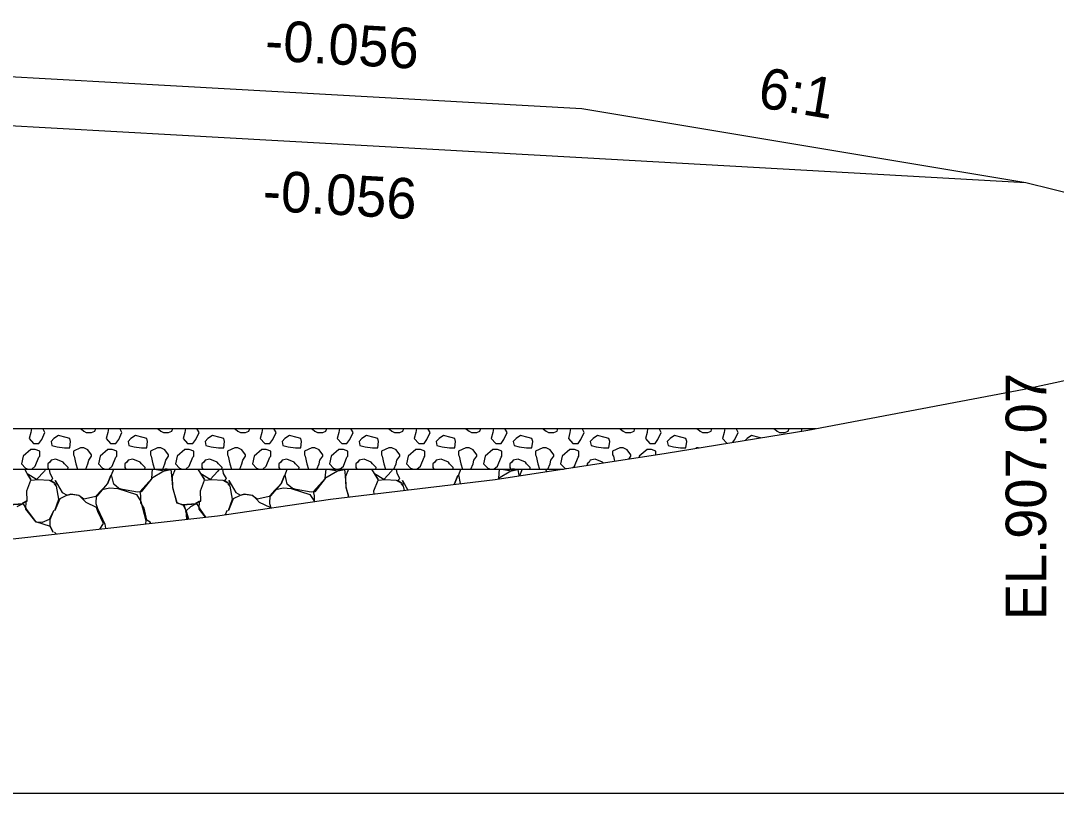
# Model space of a CAD drawing. Extents: x -26 to 4781, y -31 to 24738.
# Drawn here: x 2308.16 to 2333.7, y 8000 to 8019.06 of the extents above; entities that cross this region are included whole.
import ezdxf

# ---------------------------------------------------------------- set-up
doc = ezdxf.new("R2010")
doc.units = 0
for name, color, linetype in [('DESIGN - SHEET - Light Grid', 7, 'Continuous'), ('DESIGN - TRANSPORTATION - Proposed Layout Patterning', 7, 'Continuous'), ('DESIGN - TYPICAL - Finished Grade and Subgrade', 7, 'Continuous'), ('DESIGN - TYPICAL - Finished Grade Slopes Text', 7, 'Continuous'), ('DESIGN - TYPICAL - Subgrade Cross Slope Text', 7, 'Continuous'), ('DESIGN - TYPICAL - Subgrade Tie Text', 7, 'Continuous'), ('GEOTECHNICAL – SCRATCH – Level 1', 7, 'Continuous'), ('SURVEY - GROUND - Top of Ground', 7, 'Continuous')]:
    doc.layers.add(name, color=color, linetype=linetype)

msp = doc.modelspace()

# ---------------------------------------------------------------- linework, layer by layer
at = {"layer": 'DESIGN - SHEET - Light Grid'}
msp.add_line((2300, 8000), (2600, 8000), dxfattribs=at)
at = {"layer": 'DESIGN - TRANSPORTATION - Proposed Layout Patterning'}
for p, q in [((2308.423, 8009), (2308.407, 8008.901)), ((2310.323, 8009), (2310.307, 8008.901)), ((2312.223, 8009), (2312.207, 8008.901)), ((2314.123, 8009), (2314.107, 8008.901)), ((2316.023, 8009), (2316.007, 8008.901)), ((2317.923, 8009), (2317.907, 8008.901)), ((2319.823, 8009), (2319.807, 8008.901)), ((2321.723, 8009), (2321.707, 8008.901)), ((2323.623, 8009), (2323.607, 8008.901)), ((2325.523, 8009), (2325.507, 8008.901)), ((2327.423, 8009), (2327.413, 8008.937)), ((2327.71, 8008.989), (2327.704, 8009)), ((2308.407, 8008.481), (2308.217, 8008.321)), ((2310.307, 8008.481), (2310.117, 8008.321)), ((2312.207, 8008.481), (2312.017, 8008.321)), ((2314.107, 8008.481), (2313.917, 8008.321)), ((2316.007, 8008.481), (2315.817, 8008.321)), ((2317.907, 8008.481), (2317.717, 8008.321)), ((2319.807, 8008.481), (2319.617, 8008.321)), ((2321.707, 8008.481), (2321.517, 8008.321)), ((2323.607, 8008.481), (2323.417, 8008.321)), ((2309.457, 8008.351), (2309.477, 8008.321)), ((2311.357, 8008.351), (2311.377, 8008.321)), ((2313.257, 8008.351), (2313.277, 8008.321)), ((2315.157, 8008.351), (2315.177, 8008.321)), ((2317.057, 8008.351), (2317.077, 8008.321)), ((2318.957, 8008.351), (2318.977, 8008.321)), ((2320.857, 8008.351), (2320.877, 8008.321)), ((2322.523, 8008.15), (2322.507, 8008.171)), ((2322.757, 8008.351), (2322.777, 8008.321)), ((2322.777, 8008.321), (2322.804, 8008.193)), ((2323.156, 8008.248), (2323.207, 8008.321)), ((2323.417, 8008.321), (2323.41, 8008.287)), ((2320.528, 8008), (2320.458, 8007.833)), ((2321.135, 8007.937), (2321.1, 8008))]:
    msp.add_line(p, q, dxfattribs=at)
for points in [[(2308.407, 8008.901), (2308.367, 8008.751), (2308.477, 8008.631), (2308.607, 8008.631), (2308.677, 8008.731), (2308.757, 8008.901), (2308.704, 8009)], [(2309.609, 8009), (2309.657, 8008.981), (2309.717, 8008.931)], [(2309.717, 8008.931), (2309.777, 8008.901), (2309.907, 8008.901), (2309.987, 8008.931), (2310.01, 8009)], [(2310.307, 8008.901), (2310.267, 8008.751), (2310.377, 8008.631), (2310.507, 8008.631), (2310.577, 8008.731), (2310.657, 8008.901), (2310.604, 8009)], [(2311.509, 8009), (2311.557, 8008.981), (2311.617, 8008.931)], [(2311.617, 8008.931), (2311.677, 8008.901), (2311.807, 8008.901), (2311.887, 8008.931), (2311.91, 8009)], [(2312.207, 8008.901), (2312.167, 8008.751), (2312.277, 8008.631), (2312.407, 8008.631), (2312.477, 8008.731), (2312.557, 8008.901), (2312.504, 8009)], [(2313.409, 8009), (2313.457, 8008.981), (2313.517, 8008.931)], [(2313.517, 8008.931), (2313.577, 8008.901), (2313.707, 8008.901), (2313.787, 8008.931), (2313.81, 8009)], [(2314.107, 8008.901), (2314.067, 8008.751), (2314.177, 8008.631), (2314.307, 8008.631), (2314.377, 8008.731), (2314.457, 8008.901), (2314.404, 8009)], [(2315.309, 8009), (2315.357, 8008.981), (2315.417, 8008.931)], [(2315.417, 8008.931), (2315.477, 8008.901), (2315.607, 8008.901), (2315.687, 8008.931), (2315.71, 8009)], [(2316.007, 8008.901), (2315.967, 8008.751), (2316.077, 8008.631), (2316.207, 8008.631), (2316.277, 8008.731), (2316.357, 8008.901), (2316.304, 8009)], [(2317.209, 8009), (2317.257, 8008.981), (2317.317, 8008.931)], [(2317.317, 8008.931), (2317.377, 8008.901), (2317.507, 8008.901), (2317.587, 8008.931), (2317.61, 8009)], [(2317.907, 8008.901), (2317.867, 8008.751), (2317.977, 8008.631), (2318.107, 8008.631), (2318.177, 8008.731), (2318.257, 8008.901), (2318.204, 8009)], [(2319.109, 8009), (2319.157, 8008.981), (2319.217, 8008.931)], [(2319.217, 8008.931), (2319.277, 8008.901), (2319.407, 8008.901), (2319.487, 8008.931), (2319.51, 8009)], [(2319.807, 8008.901), (2319.767, 8008.751), (2319.877, 8008.631), (2320.007, 8008.631), (2320.077, 8008.731), (2320.157, 8008.901), (2320.104, 8009)], [(2321.009, 8009), (2321.057, 8008.981), (2321.117, 8008.931)], [(2321.117, 8008.931), (2321.177, 8008.901), (2321.307, 8008.901), (2321.387, 8008.931), (2321.41, 8009)], [(2321.707, 8008.901), (2321.667, 8008.751), (2321.777, 8008.631), (2321.907, 8008.631), (2321.977, 8008.731), (2322.057, 8008.901), (2322.004, 8009)], [(2322.909, 8009), (2322.957, 8008.981), (2323.017, 8008.931)], [(2323.017, 8008.931), (2323.077, 8008.901), (2323.207, 8008.901), (2323.287, 8008.931), (2323.31, 8009)], [(2323.607, 8008.901), (2323.567, 8008.751), (2323.677, 8008.631), (2323.807, 8008.631), (2323.877, 8008.731), (2323.957, 8008.901), (2323.904, 8009)], [(2324.809, 8009), (2324.857, 8008.981), (2324.917, 8008.931)], [(2324.917, 8008.931), (2324.977, 8008.901), (2325.107, 8008.901), (2325.187, 8008.931), (2325.21, 8009)], [(2325.507, 8008.901), (2325.467, 8008.751), (2325.574, 8008.635)], [(2325.728, 8008.66), (2325.777, 8008.731), (2325.857, 8008.901), (2325.804, 8009)], [(2326.709, 8009), (2326.757, 8008.981), (2326.817, 8008.931)], [(2326.817, 8008.931), (2326.877, 8008.901), (2327.007, 8008.901), (2327.087, 8008.931), (2327.11, 8009)], [(2309.367, 8008.751), (2309.277, 8008.781), (2309.087, 8008.831), (2308.977, 8008.751), (2308.907, 8008.681), (2308.927, 8008.581), (2309.057, 8008.551), (2309.237, 8008.521), (2309.367, 8008.521), (2309.387, 8008.681), (2309.367, 8008.751)], [(2311.267, 8008.751), (2311.177, 8008.781), (2310.987, 8008.831), (2310.877, 8008.751), (2310.807, 8008.681), (2310.827, 8008.581), (2310.957, 8008.551), (2311.137, 8008.521), (2311.267, 8008.521), (2311.287, 8008.681), (2311.267, 8008.751)], [(2313.167, 8008.751), (2313.077, 8008.781), (2312.887, 8008.831), (2312.777, 8008.751), (2312.707, 8008.681), (2312.727, 8008.581), (2312.857, 8008.551), (2313.037, 8008.521), (2313.167, 8008.521), (2313.187, 8008.681), (2313.167, 8008.751)], [(2315.067, 8008.751), (2314.977, 8008.781), (2314.787, 8008.831), (2314.677, 8008.751), (2314.607, 8008.681), (2314.627, 8008.581), (2314.757, 8008.551), (2314.937, 8008.521), (2315.067, 8008.521), (2315.087, 8008.681), (2315.067, 8008.751)], [(2316.967, 8008.751), (2316.877, 8008.781), (2316.687, 8008.831), (2316.577, 8008.751), (2316.507, 8008.681), (2316.527, 8008.581), (2316.657, 8008.551), (2316.837, 8008.521), (2316.967, 8008.521), (2316.987, 8008.681), (2316.967, 8008.751)], [(2318.867, 8008.751), (2318.777, 8008.781), (2318.587, 8008.831), (2318.477, 8008.751), (2318.407, 8008.681), (2318.427, 8008.581), (2318.557, 8008.551), (2318.737, 8008.521), (2318.867, 8008.521), (2318.887, 8008.681), (2318.867, 8008.751)], [(2320.767, 8008.751), (2320.677, 8008.781), (2320.487, 8008.831), (2320.377, 8008.751), (2320.307, 8008.681), (2320.327, 8008.581), (2320.457, 8008.551), (2320.637, 8008.521), (2320.767, 8008.521), (2320.787, 8008.681), (2320.767, 8008.751)], [(2322.667, 8008.751), (2322.577, 8008.781), (2322.387, 8008.831), (2322.277, 8008.751), (2322.207, 8008.681), (2322.227, 8008.581), (2322.357, 8008.551), (2322.537, 8008.521), (2322.667, 8008.521), (2322.687, 8008.681), (2322.667, 8008.751)], [(2324.567, 8008.751), (2324.477, 8008.781), (2324.287, 8008.831), (2324.177, 8008.751), (2324.107, 8008.681), (2324.127, 8008.581), (2324.257, 8008.551), (2324.437, 8008.521), (2324.567, 8008.521), (2324.587, 8008.681), (2324.567, 8008.751)], [(2326.405, 8008.771), (2326.377, 8008.781), (2326.187, 8008.831), (2326.077, 8008.751), (2326.038, 8008.711)], [(2308.627, 8008.321), (2308.627, 8008.441), (2308.517, 8008.481), (2308.407, 8008.481)], [(2309.717, 8008.521), (2309.657, 8008.521), (2309.637, 8008.521), (2309.457, 8008.441), (2309.457, 8008.351)], [(2309.907, 8008.321), (2309.907, 8008.351), (2309.817, 8008.471), (2309.717, 8008.521)], [(2310.527, 8008.321), (2310.527, 8008.441), (2310.417, 8008.481), (2310.307, 8008.481)], [(2311.617, 8008.521), (2311.557, 8008.521), (2311.537, 8008.521), (2311.357, 8008.441), (2311.357, 8008.351)], [(2311.807, 8008.321), (2311.807, 8008.351), (2311.717, 8008.471), (2311.617, 8008.521)], [(2312.427, 8008.321), (2312.427, 8008.441), (2312.317, 8008.481), (2312.207, 8008.481)], [(2313.517, 8008.521), (2313.457, 8008.521), (2313.437, 8008.521), (2313.257, 8008.441), (2313.257, 8008.351)], [(2313.707, 8008.321), (2313.707, 8008.351), (2313.617, 8008.471), (2313.517, 8008.521)], [(2314.327, 8008.321), (2314.327, 8008.441), (2314.217, 8008.481), (2314.107, 8008.481)], [(2315.417, 8008.521), (2315.357, 8008.521), (2315.337, 8008.521), (2315.157, 8008.441), (2315.157, 8008.351)], [(2315.607, 8008.321), (2315.607, 8008.351), (2315.517, 8008.471), (2315.417, 8008.521)], [(2316.227, 8008.321), (2316.227, 8008.441), (2316.117, 8008.481), (2316.007, 8008.481)], [(2317.317, 8008.521), (2317.257, 8008.521), (2317.237, 8008.521), (2317.057, 8008.441), (2317.057, 8008.351)], [(2317.507, 8008.321), (2317.507, 8008.351), (2317.417, 8008.471), (2317.317, 8008.521)], [(2318.127, 8008.321), (2318.127, 8008.441), (2318.017, 8008.481), (2317.907, 8008.481)], [(2319.217, 8008.521), (2319.157, 8008.521), (2319.137, 8008.521), (2318.957, 8008.441), (2318.957, 8008.351)], [(2319.407, 8008.321), (2319.407, 8008.351), (2319.317, 8008.471), (2319.217, 8008.521)], [(2320.027, 8008.321), (2320.027, 8008.441), (2319.917, 8008.481), (2319.807, 8008.481)], [(2321.117, 8008.521), (2321.057, 8008.521), (2321.037, 8008.521), (2320.857, 8008.441), (2320.857, 8008.351)], [(2321.307, 8008.321), (2321.307, 8008.351), (2321.217, 8008.471), (2321.117, 8008.521)], [(2321.927, 8008.321), (2321.927, 8008.441), (2321.817, 8008.481), (2321.707, 8008.481)], [(2323.017, 8008.521), (2322.957, 8008.521), (2322.937, 8008.521), (2322.757, 8008.441), (2322.757, 8008.351)], [(2323.207, 8008.321), (2323.207, 8008.351), (2323.117, 8008.471), (2323.017, 8008.521)], [(2323.827, 8008.351), (2323.827, 8008.441), (2323.717, 8008.481), (2323.607, 8008.481)], [(2324.879, 8008.521), (2324.857, 8008.521), (2324.837, 8008.521), (2324.813, 8008.51)], [(2308.217, 8008.321), (2308.177, 8008.131), (2308.277, 8008.021), (2308.344, 8008)], [(2308.431, 8008), (2308.517, 8008.071), (2308.607, 8008.291), (2308.627, 8008.321)], [(2309.207, 8008.171), (2309.027, 8008.241), (2308.907, 8008.221), (2308.877, 8008.171), (2308.827, 8008.131), (2308.827, 8008.041), (2308.848, 8008)], [(2309.322, 8008), (2309.327, 8008.041), (2309.237, 8008.131), (2309.207, 8008.171)], [(2309.477, 8008.321), (2309.517, 8008.131), (2309.559, 8008)], [(2309.765, 8008), (2309.817, 8008.131), (2309.837, 8008.221), (2309.907, 8008.321)], [(2310.117, 8008.321), (2310.077, 8008.131), (2310.177, 8008.021), (2310.244, 8008)], [(2310.331, 8008), (2310.417, 8008.071), (2310.507, 8008.291), (2310.527, 8008.321)], [(2311.107, 8008.171), (2310.927, 8008.241), (2310.807, 8008.221), (2310.777, 8008.171), (2310.727, 8008.131), (2310.727, 8008.041), (2310.748, 8008)], [(2311.222, 8008), (2311.227, 8008.041), (2311.137, 8008.131), (2311.107, 8008.171)], [(2311.377, 8008.321), (2311.417, 8008.131), (2311.459, 8008)], [(2311.665, 8008), (2311.717, 8008.131), (2311.737, 8008.221), (2311.807, 8008.321)], [(2312.017, 8008.321), (2311.977, 8008.131), (2312.077, 8008.021), (2312.144, 8008)], [(2312.231, 8008), (2312.317, 8008.071), (2312.407, 8008.291), (2312.427, 8008.321)], [(2313.007, 8008.171), (2312.827, 8008.241), (2312.707, 8008.221), (2312.677, 8008.171), (2312.627, 8008.131), (2312.627, 8008.041), (2312.648, 8008)], [(2313.122, 8008), (2313.127, 8008.041), (2313.037, 8008.131), (2313.007, 8008.171)], [(2313.277, 8008.321), (2313.317, 8008.131), (2313.359, 8008)], [(2313.565, 8008), (2313.617, 8008.131), (2313.637, 8008.221), (2313.707, 8008.321)], [(2313.917, 8008.321), (2313.877, 8008.131), (2313.977, 8008.021), (2314.044, 8008)], [(2314.131, 8008), (2314.217, 8008.071), (2314.307, 8008.291), (2314.327, 8008.321)], [(2314.907, 8008.171), (2314.727, 8008.241), (2314.607, 8008.221), (2314.577, 8008.171), (2314.527, 8008.131), (2314.527, 8008.041), (2314.548, 8008)], [(2315.022, 8008), (2315.027, 8008.041), (2314.937, 8008.131), (2314.907, 8008.171)], [(2315.177, 8008.321), (2315.217, 8008.131), (2315.259, 8008)], [(2315.465, 8008), (2315.517, 8008.131), (2315.537, 8008.221), (2315.607, 8008.321)], [(2315.817, 8008.321), (2315.777, 8008.131), (2315.877, 8008.021), (2315.944, 8008)], [(2316.031, 8008), (2316.117, 8008.071), (2316.207, 8008.291), (2316.227, 8008.321)], [(2316.807, 8008.171), (2316.627, 8008.241), (2316.507, 8008.221), (2316.477, 8008.171), (2316.427, 8008.131), (2316.427, 8008.041), (2316.448, 8008)], [(2316.922, 8008), (2316.927, 8008.041), (2316.837, 8008.131), (2316.807, 8008.171)], [(2317.077, 8008.321), (2317.117, 8008.131), (2317.159, 8008)], [(2317.365, 8008), (2317.417, 8008.131), (2317.437, 8008.221), (2317.507, 8008.321)], [(2317.717, 8008.321), (2317.677, 8008.131), (2317.777, 8008.021), (2317.844, 8008)], [(2317.931, 8008), (2318.017, 8008.071), (2318.107, 8008.291), (2318.127, 8008.321)], [(2318.707, 8008.171), (2318.527, 8008.241), (2318.407, 8008.221), (2318.377, 8008.171), (2318.327, 8008.131), (2318.327, 8008.041), (2318.348, 8008)], [(2318.822, 8008), (2318.827, 8008.041), (2318.737, 8008.131), (2318.707, 8008.171)], [(2318.977, 8008.321), (2319.017, 8008.131), (2319.059, 8008)], [(2319.265, 8008), (2319.317, 8008.131), (2319.337, 8008.221), (2319.407, 8008.321)], [(2319.617, 8008.321), (2319.577, 8008.131), (2319.677, 8008.021), (2319.744, 8008)], [(2319.831, 8008), (2319.917, 8008.071), (2320.007, 8008.291), (2320.027, 8008.321)], [(2320.607, 8008.171), (2320.427, 8008.241), (2320.307, 8008.221), (2320.277, 8008.171), (2320.227, 8008.131), (2320.227, 8008.041), (2320.248, 8008)], [(2320.722, 8008), (2320.727, 8008.041), (2320.637, 8008.131), (2320.607, 8008.171)], [(2320.877, 8008.321), (2320.917, 8008.131), (2320.959, 8008)], [(2321.165, 8008), (2321.217, 8008.131), (2321.237, 8008.221), (2321.307, 8008.321)], [(2321.517, 8008.321), (2321.477, 8008.131), (2321.577, 8008.021), (2321.611, 8008.01)], [(2321.774, 8008.035), (2321.817, 8008.071), (2321.907, 8008.291), (2321.927, 8008.321)], [(2322.507, 8008.171), (2322.327, 8008.241), (2322.207, 8008.221), (2322.177, 8008.171), (2322.127, 8008.131), (2322.127, 8008.089)], [(2308.072, 8007.079), (2308.202, 8007.139), (2307.872, 8007.119), (2308.222, 8007.139), (2308.302, 8006.999), (2308.522, 8006.709), (2308.882, 8006.589), (2308.962, 8006.439), (2308.882, 8006.579), (2308.882, 8006.759), (2308.972, 8006.979), (2308.862, 8006.759), (2308.692, 8006.679), (2308.542, 8006.689), (2308.282, 8007.009), (2308.292, 8007.209), (2308.202, 8007.159), (2308.322, 8007.209), (2308.312, 8007.459), (2308.412, 8007.729), (2308.592, 8007.739), (2308.862, 8007.729), (2308.992, 8007.649), (2308.902, 8007.719), (2308.952, 8007.769), (2308.882, 8007.889), (2308.868, 8008)], [(2308.77, 8008), (2308.742, 8007.949), (2308.552, 8007.739), (2308.322, 8007.879), (2308.412, 8007.739), (2308.322, 8007.889), (2308.26, 8008)], [(2311.365, 8006.663), (2311.352, 8006.689), (2311.272, 8006.739), (2311.202, 8007.039), (2311.122, 8007.169), (2311.122, 8007.339), (2311.102, 8007.449), (2311.392, 8007.769), (2311.132, 8007.439), (2311.042, 8007.429), (2310.672, 8007.499), (2310.582, 8007.519), (2310.452, 8007.629), (2310.402, 8007.859), (2310.452, 8007.999), (2310.452, 8008)], [(2311.402, 8008), (2311.402, 8007.999), (2311.382, 8007.779), (2311.692, 8007.959), (2311.783, 8008)], [(2311.455, 8008), (2311.702, 8007.959), (2311.862, 8007.989), (2311.882, 8007.839), (2311.902, 8007.559), (2312.002, 8007.169), (2312.182, 8007.119), (2312.232, 8006.969), (2312.249, 8006.763)], [(2311.775, 8008), (2311.772, 8007.999), (2311.725, 8008)], [(2311.968, 8008), (2311.892, 8007.819), (2311.902, 8007.549), (2312.012, 8007.179), (2312.162, 8007.109), (2312.242, 8006.959), (2312.294, 8006.768)], [(2312.719, 8006.816), (2312.562, 8007.009), (2312.572, 8007.209), (2312.482, 8007.159), (2312.602, 8007.209), (2312.592, 8007.459), (2312.692, 8007.729), (2312.872, 8007.739), (2313.142, 8007.729), (2313.272, 8007.649), (2313.182, 8007.719), (2313.232, 8007.769), (2313.162, 8007.889), (2313.148, 8008)], [(2313.05, 8008), (2313.022, 8007.949), (2312.832, 8007.739), (2312.602, 8007.879), (2312.692, 8007.739), (2312.602, 8007.889), (2312.54, 8008)], [(2315.402, 8007.197), (2315.402, 8007.339), (2315.382, 8007.449), (2315.672, 8007.769), (2315.412, 8007.439), (2315.322, 8007.429), (2314.952, 8007.499), (2314.862, 8007.519), (2314.732, 8007.629), (2314.682, 8007.859), (2314.732, 8007.999), (2314.732, 8008)], [(2315.682, 8008), (2315.682, 8007.999), (2315.662, 8007.779), (2315.972, 8007.959), (2316.063, 8008)], [(2315.735, 8008), (2315.982, 8007.959), (2316.142, 8007.989), (2316.162, 8007.839), (2316.182, 8007.559), (2316.247, 8007.309)], [(2316.055, 8008), (2316.052, 8007.999), (2316.005, 8008)], [(2316.248, 8008), (2316.172, 8007.819), (2316.182, 8007.549), (2316.254, 8007.31)], [(2317.33, 8008), (2317.302, 8007.949), (2317.112, 8007.739), (2316.882, 8007.879), (2316.972, 8007.739), (2316.882, 8007.889), (2316.82, 8008)], [(2316.875, 8007.384), (2316.872, 8007.459), (2316.972, 8007.729), (2317.152, 8007.739), (2317.422, 8007.729), (2317.552, 8007.649), (2317.462, 8007.719), (2317.512, 8007.769), (2317.442, 8007.889), (2317.428, 8008)], [(2319.01, 8007.64), (2318.962, 8007.859), (2319.012, 8007.999), (2319.012, 8008)], [(2319.962, 8008), (2319.962, 8007.999), (2319.942, 8007.779), (2320.252, 8007.959), (2320.343, 8008)], [(2320.015, 8008), (2320.262, 8007.959), (2320.422, 8007.989), (2320.442, 8007.839), (2320.443, 8007.831)], [(2320.335, 8008), (2320.332, 8007.999), (2320.285, 8008)], [(2310.108, 8006.521), (2310.202, 8006.659), (2310.062, 8006.949), (2310.032, 8007.049), (2309.772, 8007.179), (2309.692, 8007.259), (2309.602, 8007.349), (2309.392, 8007.379), (2309.292, 8007.349), (2309.122, 8007.269), (2309.002, 8006.979), (2309.102, 8007.259), (2309.042, 8007.579), (2308.992, 8007.639), (2309.052, 8007.639), (2309.012, 8007.719), (2309.182, 8007.419), (2309.302, 8007.359), (2309.402, 8007.379), (2309.592, 8007.359), (2309.712, 8007.269), (2310.052, 8007.339), (2310.302, 8007.639), (2310.382, 8007.839), (2310.302, 8007.639), (2310.142, 8007.469), (2310.022, 8007.339), (2310.012, 8007.149), (2310.052, 8007.029), (2310.232, 8006.639), (2310.252, 8006.538)], [(2314.315, 8007.039), (2314.312, 8007.049), (2314.052, 8007.179), (2313.972, 8007.259), (2313.882, 8007.349), (2313.672, 8007.379), (2313.572, 8007.349), (2313.402, 8007.269), (2313.282, 8006.979), (2313.382, 8007.259), (2313.322, 8007.579), (2313.272, 8007.639), (2313.332, 8007.639), (2313.292, 8007.719), (2313.462, 8007.419), (2313.582, 8007.359), (2313.682, 8007.379), (2313.872, 8007.359), (2313.992, 8007.269), (2314.332, 8007.339), (2314.582, 8007.639), (2314.662, 8007.839), (2314.582, 8007.639), (2314.422, 8007.469), (2314.302, 8007.339), (2314.292, 8007.149), (2314.329, 8007.041)], [(2317.622, 8007.473), (2317.602, 8007.579), (2317.552, 8007.639), (2317.612, 8007.639), (2317.572, 8007.719), (2317.706, 8007.483)], [(2318.847, 8007.62), (2318.862, 8007.639), (2318.942, 8007.839), (2318.862, 8007.639), (2318.845, 8007.62)], [(2319.938, 8007.753), (2319.952, 8007.769), (2319.941, 8007.754)], [(2310.172, 8007.499), (2310.352, 8007.539), (2310.552, 8007.519), (2311.012, 8007.369), (2311.122, 8007.199), (2311.242, 8006.729), (2311.234, 8006.648)], [(2314.452, 8007.499), (2314.632, 8007.539), (2314.832, 8007.519), (2315.292, 8007.369), (2315.402, 8007.199), (2315.403, 8007.197)], [(2312.287, 8006.767), (2312.232, 8006.959), (2312.352, 8007.079), (2312.482, 8007.139), (2312.152, 8007.119), (2312.502, 8007.139), (2312.582, 8006.999), (2312.721, 8006.816)], [(2313.211, 8006.878), (2313.252, 8006.979), (2313.201, 8006.876)], [(2309.037, 8006.401), (2308.992, 8006.439), (2309.031, 8006.4)]]:
    msp.add_lwpolyline(points, dxfattribs=at)
at = {"layer": 'DESIGN - TYPICAL - Finished Grade and Subgrade'}
for p, q in [((2302, 8018.019), (2312, 8017.457)), ((2312, 8017.457), (2322, 8016.896)), ((2322, 8016.896), (2332.953, 8015.07)), ((2302, 8016.809), (2312, 8016.247)), ((2312, 8016.247), (2322, 8015.686)), ((2322, 8015.686), (2332.953, 8015.07)), ((2332.953, 8015.07), (2350.633, 8010.65))]:
    msp.add_line(p, q, dxfattribs=at)
at = {"layer": 'GEOTECHNICAL – SCRATCH – Level 1'}
for p, q in [((2245.256, 8009), (2327.768, 8009)), ((2242.256, 8008), (2321.545, 8008))]:
    msp.add_line(p, q, dxfattribs=at)
at = {"layer": 'SURVEY - GROUND - Top of Ground'}
msp.add_lwpolyline([(2277.589, 8003.696), (2282.868, 8004.002), (2286.458, 8004.226), (2289.45, 8004.443), (2294.985, 8004.902), (2300, 8005.41), (2301.616, 8005.573), (2302.481, 8005.673), (2303.129, 8005.735), (2313.014, 8006.849), (2315.802, 8007.256), (2319.862, 8007.741), (2324.083, 8008.39), (2327.572, 8008.963), (2332.911, 8009.975), (2336.765, 8010.805)], dxfattribs=at)

# ---------------------------------------------------------------- texts
at = {"layer": 'DESIGN - TYPICAL - Finished Grade Slopes Text'}
for s, rotation, p in [('-0.056', 356.7838, (2314.167, 8018.086)), ('6:1', 350.5377, (2326.311, 8016.937))]:
    msp.add_text(s, height=1, rotation=rotation, dxfattribs=at).set_placement(p)
at = {"layer": 'DESIGN - TYPICAL - Subgrade Cross Slope Text'}
msp.add_text('-0.056', height=1, rotation=356.7838, dxfattribs=at).set_placement((2314.111, 8014.377))
at = {"layer": 'DESIGN - TYPICAL - Subgrade Tie Text'}
msp.add_text('EL.907.07', height=1, rotation=90, dxfattribs=at).set_placement((2333.453, 8004.272))

doc.saveas('drawing.dxf')
